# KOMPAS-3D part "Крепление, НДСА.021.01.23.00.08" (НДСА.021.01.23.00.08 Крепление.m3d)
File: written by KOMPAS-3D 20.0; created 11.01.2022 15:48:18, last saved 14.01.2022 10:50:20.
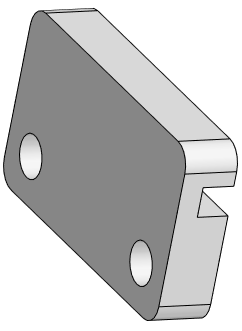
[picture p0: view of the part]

Document properties: Полное имя файла: C:\Users\gornostaev\Desktop\PLM\НДСА.021.01.23.00.08 Крепление.m3d

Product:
- Part/product: Крепление  | designation НДСА.021.01.23.00.08
    Материал: АМг6  ГОСТ 4784-2019 (density 2640 kg/m3)
    Масса: 0.076235
    additional columns: <item xmlns="http://appius.ru/pdm" xmlns:xs="http://www.w3.org/2001/XMLSchema" x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; <item xmlns="http://appius.ru/pdm" xmlns:xs="http://www.w3.org/2001/XMLSchema" x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; <item xmlns="http://appius.ru/pdm" xmlns:xs="http://www.w3.org/2001/XMLSchema" x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
    source file: НДСА.021.01.23.00.08 Крепление.cdw

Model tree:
1. Эскиз:1
2. Элемент выдавливания:1
     Расстояние 1 = 12
3. Эскиз:2  (with: Элемент выдавливания:1)
4. Элемент выдавливания:2
     Расстояние 2 = 6
5. Эскиз:3  (with: Элемент выдавливания:1)
6. Элемент выдавливания:3
7. Скругление:1  (with: Элемент выдавливания:1)  (labels: АМг6  ГОСТ 4784-2019)
     Радиус = 5

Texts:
  НДСА.021.01.23.00.08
